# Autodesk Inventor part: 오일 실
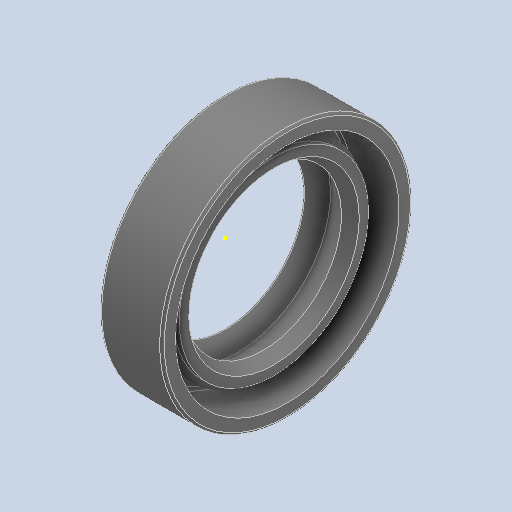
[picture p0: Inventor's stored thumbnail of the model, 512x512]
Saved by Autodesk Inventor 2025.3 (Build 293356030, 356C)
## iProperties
Created: 2025-08
Part Number: 오일 실
Material: 고무
Description: 오일-실
Document SubType Name: Modeling
Designer: user
Density: 0.93 g/cm^3
Appearance: 기본값
Sending System: Autodesk Inventor 2026
Preprocessor: ST-DEVELOPER v20.1
Author: jhkim
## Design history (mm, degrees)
sketch "스케치1"
  geometry: 1 further point
  constraints: 1 other
feature "Solid1"
node "솔리드1"
